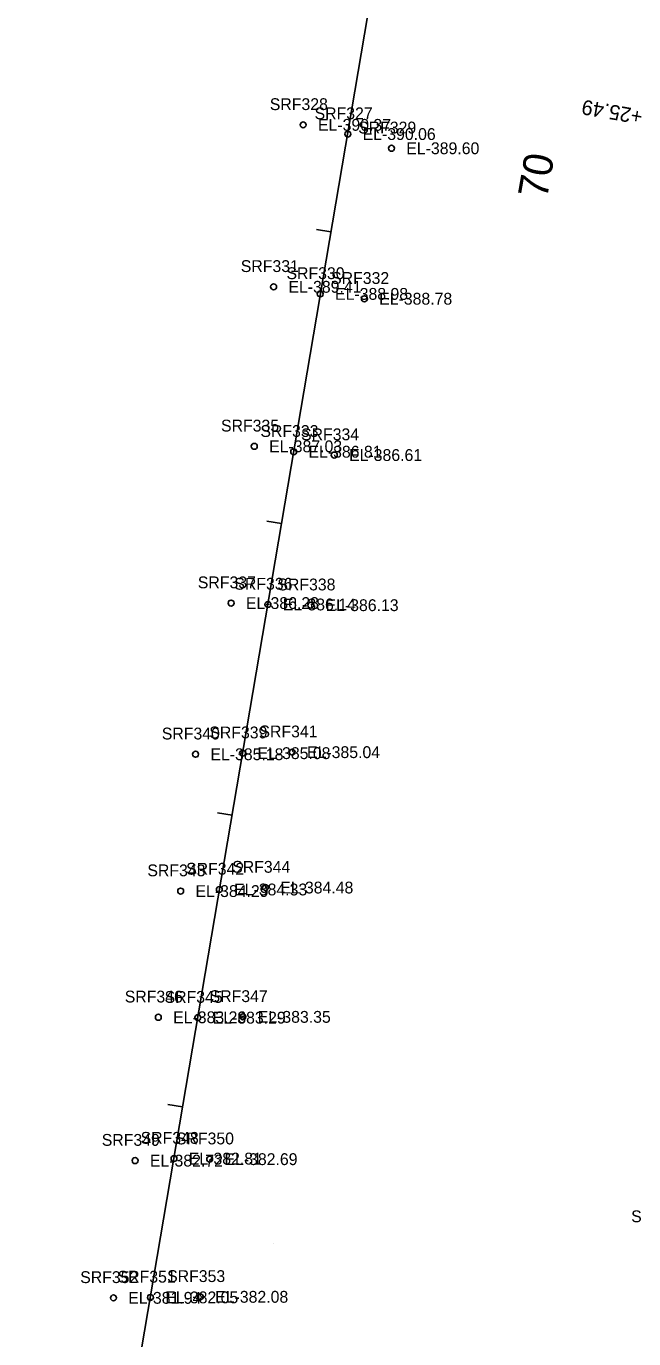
# Model space of a CAD drawing. Extents: x 1189978 to 1314812, y 571533 to 629339.
# Drawn here: x 1217329.5 to 1217534.8, y 622363.9 to 622807.5 of the extents above; entities that cross this region are included whole.
import ezdxf

# ---------------------------------------------------------------- set-up
doc = ezdxf.new("R2010")
doc.units = 0
for name, color, linetype in [('Default', 7, 'Continuous'), ('SURVEY - CENTERLINE - Preliminary Curve Text', 7, 'Continuous'), ('SURVEY - CENTERLINE - Preliminary Text', 7, 'Continuous'), ('SURVEY - DRAINAGE - Bridge Hydraulic Data with Text', 7, 'Continuous'), ('SURVEY - DTM - Spot Points - Elevations', 7, 'Continuous'), ('SURVEY - DTM - Spot Points - Locators', 7, 'Continuous'), ('SURVEY - DTM - Spot Points - Point Numbers', 7, 'Continuous')]:
    doc.layers.add(name, color=color, linetype=linetype)

msp = doc.modelspace()

# ---------------------------------------------------------------- linework, layer by layer
at = {"layer": 'Default'}
msp.add_line((1217412.91, 622395.9), (1217412.91, 622395.9), dxfattribs=at)
at = {"layer": 'SURVEY - DRAINAGE - Bridge Hydraulic Data with Text'}
for p, q in [((1216830.75, 619188.62), (1217464.89, 622929.19)), ((1216830.75, 619188.62), (1217464.89, 622929.19)), ((1217432.48, 622737.98), (1217427.55, 622738.82)), ((1217415.76, 622639.39), (1217410.83, 622640.22)), ((1217399.05, 622540.79), (1217394.12, 622541.63)), ((1217382.33, 622442.2), (1217377.4, 622443.04))]:
    msp.add_line(p, q, dxfattribs=at)
at = {"layer": 'SURVEY - DTM - Spot Points - Locators'}
for centre in [(1217423.08, 622774.18), (1217438.17, 622771.07), (1217452.92, 622766.27), (1217413.09, 622719.44), (1217428.85, 622717.04), (1217443.76, 622715.41), (1217406.56, 622665.52), (1217419.87, 622663.69), (1217433.59, 622662.57), (1217398.72, 622612.53), (1217411.18, 622612.06), (1217425.64, 622611.82), (1217386.73, 622561.43), (1217402.62, 622561.8), (1217419.38, 622562.14), (1217381.68, 622515.18), (1217394.76, 622515.72), (1217410.34, 622516.37), (1217374.14, 622472.52), (1217387.49, 622472.4), (1217402.72, 622472.66), (1217366.28, 622424.07), (1217379.44, 622424.75), (1217391.48, 622424.56), (1217358.98, 622377.68), (1217371.46, 622377.83), (1217388.35, 622378.03)]:
    msp.add_circle(centre, 1, dxfattribs=at)

# ---------------------------------------------------------------- texts
at = {"layer": 'SURVEY - CENTERLINE - Preliminary Curve Text'}
msp.add_text('POT 70+25.49', height=5, rotation=170.1256, dxfattribs=at).set_placement((1217560.77, 622775.25))
at = {"layer": 'SURVEY - CENTERLINE - Preliminary Text'}
msp.add_text('70', height=10, rotation=80.1256, dxfattribs=at).set_placement((1217505.43, 622748.93))
at = {"layer": 'SURVEY - DTM - Spot Points - Elevations'}
for s, p in [('EL-390.37', (1217428.08, 622772.18)), ('EL-390.06', (1217443.17, 622769.07)), ('EL-389.60', (1217457.92, 622764.27)), ('EL-389.41', (1217418.09, 622717.44)), ('EL-388.98', (1217433.85, 622715.04)), ('EL-388.78', (1217448.76, 622713.41)), ('EL-387.03', (1217411.56, 622663.52)), ('EL-386.81', (1217424.87, 622661.69)), ('EL-386.61', (1217438.59, 622660.57)), ('EL-386.28', (1217403.72, 622610.53)), ('EL-386.14', (1217416.18, 622610.06)), ('EL-386.13', (1217430.64, 622609.82)), ('EL-385.08', (1217407.62, 622559.8)), ('EL-385.04', (1217424.38, 622560.14)), ('EL-385.18', (1217391.73, 622559.43)), ('EL-384.29', (1217386.68, 622513.18)), ('EL-384.33', (1217399.76, 622513.72)), ('EL-384.48', (1217415.34, 622514.37)), ('EL-383.26', (1217379.14, 622470.52)), ('EL-383.29', (1217392.49, 622470.4)), ('EL-383.35', (1217407.72, 622470.66)), ('EL-382.72', (1217371.28, 622422.07)), ('EL-382.81', (1217384.44, 622422.75)), ('EL-382.69', (1217396.48, 622422.56)), ('EL-381.94', (1217363.98, 622375.68)), ('EL-382.05', (1217376.46, 622375.83)), ('EL-382.08', (1217393.35, 622376.03))]:
    msp.add_text(s, height=4, dxfattribs=at).set_placement(p)
at = {"layer": 'SURVEY - DTM - Spot Points - Point Numbers'}
for s, p in [('SRF328', (1217411.8, 622779.18)), ('SRF327', (1217426.93, 622776.07)), ('SRF329', (1217441.66, 622771.27)), ('SRF331', (1217402, 622724.44)), ('SRF330', (1217417.44, 622722.04)), ('SRF332', (1217432.52, 622720.41)), ('SRF335', (1217395.32, 622670.52)), ('SRF333', (1217408.63, 622668.69)), ('SRF334', (1217422.36, 622667.57)), ('SRF337', (1217387.48, 622617.53)), ('SRF336', (1217399.83, 622617.06)), ('SRF338', (1217414.36, 622616.82)), ('SRF340', (1217375.31, 622566.43)), ('SRF339', (1217391.36, 622566.8)), ('SRF341', (1217408.3, 622567.14)), ('SRF343', (1217370.44, 622520.18)), ('SRF342', (1217383.52, 622520.72)), ('SRF344', (1217399.1, 622521.37)), ('SRF346', (1217362.79, 622477.52)), ('SRF345', (1217376.25, 622477.4)), ('SRF347', (1217391.48, 622477.66)), ('SRF349', (1217355.02, 622429.07)), ('SRF348', (1217368.16, 622429.75)), ('SRF350', (1217380.07, 622429.56)), ('SMA199', (1217533.9, 622403.24)), ('SRF352', (1217347.74, 622382.68)), ('SRF351', (1217360.38, 622382.83)), ('SRF353', (1217377.11, 622383.03))]:
    msp.add_text(s, height=4, dxfattribs=at).set_placement(p)

doc.saveas('drawing.dxf')
